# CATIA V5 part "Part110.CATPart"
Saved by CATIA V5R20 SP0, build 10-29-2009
Part number: FA 063200-1
Revision: ANY
Definition: UNKNOWN
Nomenclature: FA 063200-1
Source: Unknown
Bounding box of the stored display mesh (mm): x -2.5 to 2.5, y 0.15 to 2.5, z -2.5 to 2.5
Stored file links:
  C:\Users\Utente\Desktop\IO LAVORO\3D X SITO CF\CUMSA\3D files FA\FA 063212-20\Part110.CATPart

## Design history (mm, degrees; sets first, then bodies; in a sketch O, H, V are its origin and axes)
Body1 "Cortar-Extruir1" (main body)
  Solid1: solid without history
